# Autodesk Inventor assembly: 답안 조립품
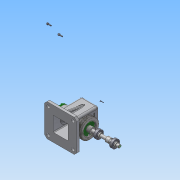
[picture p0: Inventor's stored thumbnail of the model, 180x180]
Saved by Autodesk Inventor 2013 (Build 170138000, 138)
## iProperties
Created: 2016-02
Part Number: 답안 조립품
Document SubType Name: Assembly
Designer: Administrator
Author: Administrator
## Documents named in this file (16)
- C:\Users\Administrator\Desktop\460212V1024\답안 조립품.iam
- C:\Users\Administrator\Desktop\460212V1024\본체.ipt
- C:\Users\Administrator\Desktop\460212V1024\V벨트풀리.ipt
- C:\Users\Administrator\Desktop\460212V1024\고정핀 1.2 x 10.ipt
- C:\Users\Administrator\Desktop\460212V1024\뒤커버.ipt
- C:\Users\Administrator\Desktop\460212V1024\링크.ipt
- C:\Users\Administrator\Desktop\460212V1024\멈춤나사 M3x8.ipt
- C:\Users\Administrator\Desktop\460212V1024\베어링 12 x 32 x 10.ipt
- C:\Users\Administrator\Desktop\460212V1024\볼트 M4 x 12.ipt
- C:\Users\Administrator\Desktop\460212V1024\부시.ipt
- C:\Users\Administrator\Desktop\460212V1024\슬라이드.ipt
- C:\Users\Administrator\Desktop\460212V1024\앞커버.ipt
- C:\Users\Administrator\Desktop\460212V1024\오일실 12 25 7.ipt
- C:\Users\Administrator\Desktop\460212V1024\키 4 x 4 x 10.ipt
- C:\Users\Administrator\Desktop\460212V1024\편심축.ipt
- C:\Users\Administrator\Desktop\460212V1024\핀 5 x 18.ipt
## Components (5 placed, 4 different names)
1. V벨트풀리:1
2. 고정핀 1.2 x 10:1
3. ISO 4762 M4 x 12:1
4. 핀 5 x 18:1
5. ISO 4762 M4 x 12:2
